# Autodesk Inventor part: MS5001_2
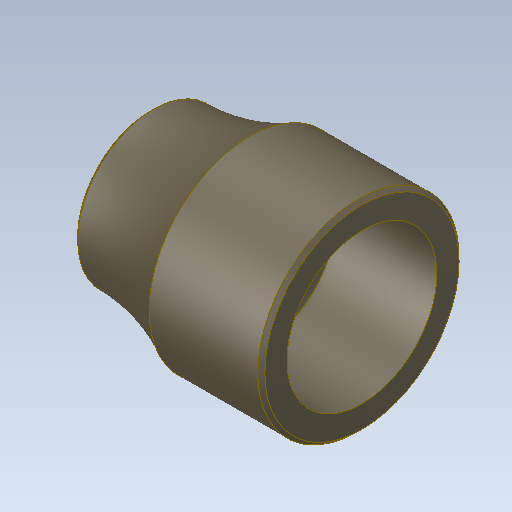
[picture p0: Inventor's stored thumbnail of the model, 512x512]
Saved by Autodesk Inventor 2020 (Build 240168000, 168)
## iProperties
Created: 2015-11
Part Number: MS5001_2
Material: Ogólny
Document SubType Name: Modeling
Designer: Tomasz
Density: 1 g/cm^3
Appearance: Domyślna
Sending System: SolidWorks 2017
Last Author: Tomasz
Last Saved: 2017-09-17
Author: Tomasz
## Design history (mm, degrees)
feature "Imported1"
node "Bryła1"
